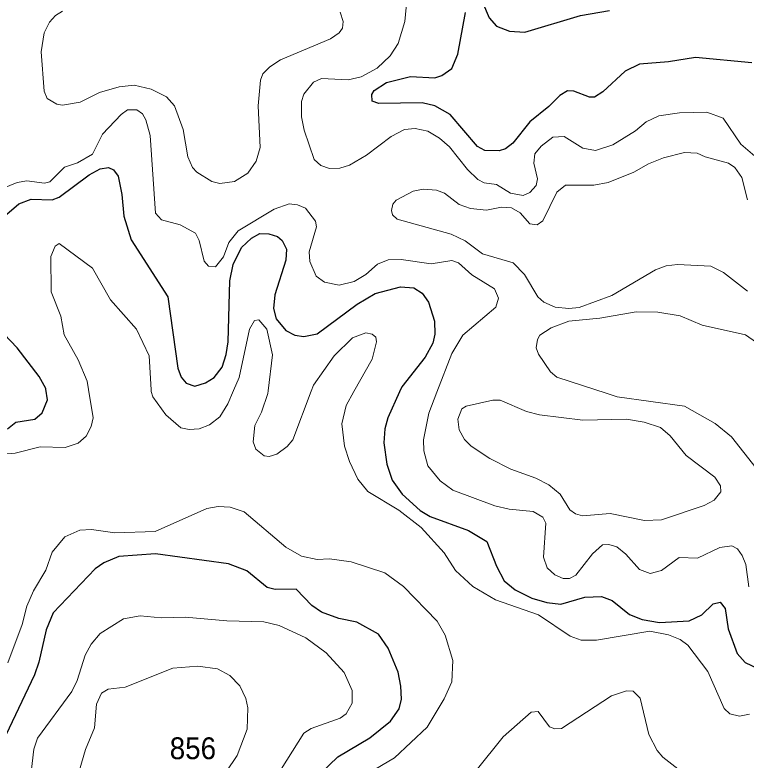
# Model space of a CAD drawing. Extents: x 473.9 to 500, y 7733.1 to 7760.8.
# Drawn here: x 494.647 to 497.324, y 7746.506 to 7749.235 of the extents above; entities that cross this region are included whole.
import ezdxf

# ---------------------------------------------------------------- set-up
doc = ezdxf.new("R2010")
doc.units = 0
doc.header["$LTSCALE"] = 0.032
doc.layers.add('1', color=7, linetype='Continuous', lineweight=25)
doc.layers.add('2', color=7, linetype='Continuous', lineweight=13)
doc.layers.add('21', color=7, linetype='Continuous')

msp = doc.modelspace()

# ---------------------------------------------------------------- linework, layer by layer
at = {"layer": '1'}
for points in [[(496.3589, 7749.2817), (496.3837, 7749.2245), (496.4099, 7749.194), (496.4582, 7749.175), (496.5134, 7749.1722), (496.717, 7749.2323), (496.8231, 7749.2508)], [(497.3442, 7749.0592), (497.1383, 7749.0787), (497.0392, 7749.0628), (496.9332, 7749.0539), (496.8806, 7749.0293), (496.799, 7748.9526), (496.7687, 7748.9331), (496.7501, 7748.9337), (496.6929, 7748.9551), (496.6695, 7748.9573), (496.6416, 7748.9401), (496.6022, 7748.8994), (496.5316, 7748.8437), (496.4703, 7748.7654), (496.4432, 7748.7448), (496.4201, 7748.7368), (496.3679, 7748.7384), (496.3407, 7748.753), (496.24, 7748.8697), (496.1842, 7748.9023), (496.1378, 7748.9131), (495.9789, 7748.9101), (495.9555, 7748.919), (495.9537, 7748.9432), (495.9624, 7748.9585), (496.0069, 7748.9879), (496.0954, 7749.0096), (496.1841, 7749.0043), (496.2094, 7749.0129), (496.2467, 7749.0384), (496.2691, 7749.0915), (496.2965, 7749.2439)], [(494.6097, 7748.498), (494.6614, 7748.5426), (494.7073, 7748.5604), (494.7835, 7748.5579), (494.8099, 7748.5673), (494.9193, 7748.6492), (494.9591, 7748.6714), (494.9904, 7748.6758), (495.0077, 7748.667), (495.0257, 7748.6441), (495.0392, 7748.5777), (495.0466, 7748.4979), (495.0732, 7748.4113), (495.2067, 7748.203), (495.2439, 7747.9411), (495.2563, 7747.9085), (495.274, 7747.887), (495.306, 7747.8754), (495.3448, 7747.8883), (495.3771, 7747.9069), (495.4056, 7747.945), (495.4207, 7747.991), (495.4276, 7748.0383), (495.4335, 7748.2606), (495.4456, 7748.321), (495.4768, 7748.3833), (495.5139, 7748.4176), (495.5437, 7748.434), (495.5772, 7748.4336), (495.608, 7748.4239), (495.6256, 7748.4083), (495.6417, 7748.3769), (495.6386, 7748.3368), (495.5987, 7748.2094), (495.5938, 7748.1602), (495.6041, 7748.1218), (495.6387, 7748.0789), (495.6718, 7748.0628), (495.7052, 7748.0578), (495.7532, 7748.0676), (495.9002, 7748.1763), (495.9658, 7748.2145), (496.0587, 7748.239), (496.1076, 7748.2357), (496.138, 7748.2166), (496.1613, 7748.1837), (496.1836, 7748.1138), (496.1845, 7748.0657), (496.1768, 7748.0332), (496.1491, 7747.9823), (496.0641, 7747.8732), (496.0556, 7747.8546), (496.012, 7747.76), (496.001, 7747.7189), (495.9981, 7747.6678), (496.0083, 7747.5896), (496.0283, 7747.5317), (496.0643, 7747.4806), (496.1306, 7747.4208), (496.1673, 7747.398), (496.3076, 7747.3469), (496.375, 7747.3063), (496.41, 7747.2164), (496.4387, 7747.1631), (496.4778, 7747.1296), (496.5391, 7747.0994), (496.5942, 7747.083), (496.6452, 7747.0777), (496.7331, 7747.1032), (496.7938, 7747.1056), (496.8333, 7747.0904), (496.8967, 7747.0393), (496.9434, 7747.0212), (497.0065, 7747.0102), (497.1153, 7747.0164), (497.1615, 7747.0381), (497.2035, 7747.079), (497.2287, 7747.0841)], [(494.6204, 7747.7197), (494.6508, 7747.7437), (494.7204, 7747.7548), (494.7468, 7747.7775), (494.7669, 7747.8251), (494.7603, 7747.8646), (494.76, 7747.8666), (494.7357, 7747.9106), (494.656, 7748.0154), (494.5833, 7748.0904)], [(495.7034, 7746.3978), (495.8295, 7746.518), (495.9467, 7746.5883), (496.0219, 7746.6492), (496.0532, 7746.6944), (496.0621, 7746.729), (496.0601, 7746.7772), (496.0499, 7746.8281), (496.0138, 7746.9158), (495.978, 7746.9673), (495.8989, 7747.0112), (495.8326, 7747.0247), (495.7691, 7747.0482), (495.7345, 7747.0728), (495.6762, 7747.1328), (495.5999, 7747.1311), (495.571, 7747.1379), (495.4963, 7747.199), (495.4296, 7747.2247), (495.1623, 7747.2616), (495.0276, 7747.2521), (494.9733, 7747.2289), (494.9413, 7747.207), (494.7874, 7747.0453), (494.7616, 7746.9839), (494.7349, 7746.8655), (494.7185, 7746.8184), (494.6146, 7746.5974)], [(497.2287, 7747.0841), (497.2465, 7747.0615), (497.2581, 7746.987), (497.2905, 7746.8971), (497.3198, 7746.8643), (497.3637, 7746.8436)]]:
    msp.add_lwpolyline(points, dxfattribs=at)
at = {"layer": '2'}
for points in [[(496.5081, 7748.5732), (496.4615, 7748.5825), (496.4095, 7748.6139), (496.3651, 7748.6204), (496.3416, 7748.6323), (496.3036, 7748.6692), (496.2379, 7748.7513), (496.202, 7748.7837), (496.1585, 7748.809), (496.112, 7748.8191), (496.0739, 7748.8152), (496.024, 7748.7893), (495.934, 7748.7213), (495.8721, 7748.6841), (495.837, 7748.6738), (495.7984, 7748.6721), (495.7669, 7748.6832), (495.7424, 7748.7055), (495.7057, 7748.8133), (495.6959, 7748.862), (495.6968, 7748.9178), (495.7052, 7748.9443), (495.7405, 7748.9888), (495.77, 7749.0016), (495.867, 7748.9977), (495.9147, 7749.0084), (495.9731, 7749.0395), (496.0209, 7749.0856), (496.0497, 7749.13), (496.0745, 7749.2111), (496.0836, 7749.3016)], [(494.8218, 7749.2485), (494.7964, 7749.233), (494.7739, 7749.208), (494.7544, 7749.1687), (494.743, 7749.1), (494.7544, 7748.9553), (494.7653, 7748.9284), (494.8009, 7748.9082), (494.8212, 7748.9044), (494.8856, 7748.9155), (494.9565, 7748.951), (495.0292, 7748.9721), (495.0837, 7748.9775), (495.1456, 7748.9633), (495.2024, 7748.9351), (495.2319, 7748.9021), (495.2637, 7748.8148), (495.2799, 7748.7152), (495.2978, 7748.6761), (495.3134, 7748.6588), (495.3682, 7748.6254), (495.3972, 7748.6173), (495.4511, 7748.625), (495.4993, 7748.6558), (495.5299, 7748.6996), (495.5453, 7748.749), (495.5374, 7748.9022), (495.5461, 7748.9954), (495.5545, 7749.0192), (495.5799, 7749.045), (495.6198, 7749.0703), (495.8021, 7749.1477), (495.834, 7749.169), (495.846, 7749.1862), (495.8483, 7749.2113), (495.838, 7749.2453)], [(494.6014, 7748.5988), (494.6552, 7748.6218), (494.691, 7748.627), (494.7553, 7748.6182), (494.7752, 7748.6242), (494.8283, 7748.6773), (494.8759, 7748.6927), (494.9307, 7748.7248), (494.9682, 7748.7982), (495.0357, 7748.8706), (495.0595, 7748.8876), (495.0932, 7748.887), (495.1141, 7748.8723), (495.1266, 7748.8508), (495.1426, 7748.7929), (495.1617, 7748.509), (495.1838, 7748.4845), (495.2522, 7748.4657), (495.3088, 7748.4359), (495.322, 7748.4086), (495.3397, 7748.3336), (495.3559, 7748.3154), (495.381, 7748.3124), (495.4102, 7748.3489), (495.4298, 7748.401), (495.4649, 7748.4448), (495.5967, 7748.5235), (495.6507, 7748.5433), (495.682, 7748.5397), (495.7113, 7748.5274), (495.7479, 7748.4798), (495.7512, 7748.4591), (495.7247, 7748.3668), (495.727, 7748.3325), (495.7505, 7748.2789), (495.7801, 7748.2566), (495.8338, 7748.2459), (495.889, 7748.2586), (495.932, 7748.2846), (495.9741, 7748.3228), (496.0133, 7748.3375), (496.0615, 7748.3391), (496.1704, 7748.3238), (496.246, 7748.3359), (496.2711, 7748.3267), (496.3197, 7748.2837), (496.4023, 7748.2314), (496.4169, 7748.1979), (496.4071, 7748.1648), (496.2863, 7748.0627), (496.2462, 7747.9949), (496.1919, 7747.8536), (496.1622, 7747.7761), (496.1426, 7747.6794), (496.1436, 7747.6388), (496.1592, 7747.5837), (496.2034, 7747.5284), (496.2508, 7747.4945), (496.4035, 7747.4372), (496.4567, 7747.4248), (496.5444, 7747.4172), (496.5802, 7747.3963), (496.5912, 7747.3742), (496.5824, 7747.2495), (496.5955, 7747.2108), (496.6232, 7747.1843), (496.6539, 7747.171), (496.6772, 7747.1719), (496.7009, 7747.1832), (496.7619, 7747.2619), (496.798, 7747.2949), (496.8209, 7747.2964)], [(497.364, 7748.7098), (497.304, 7748.7612), (497.2392, 7748.8569), (497.1803, 7748.8787), (497.0794, 7748.8769), (497.0044, 7748.865), (496.9583, 7748.8429), (496.9184, 7748.8105), (496.8361, 7748.7594), (496.7719, 7748.7378), (496.7262, 7748.7472), (496.6572, 7748.7902), (496.6163, 7748.7868), (496.5733, 7748.754), (496.5506, 7748.7267), (496.547, 7748.6917), (496.5599, 7748.6344), (496.5551, 7748.6099), (496.5317, 7748.5848), (496.5081, 7748.5732)], [(497.3282, 7748.2228), (497.2405, 7748.2919), (497.1952, 7748.3149), (497.0725, 7748.3214), (497.0312, 7748.3162), (496.9922, 7748.301), (496.8324, 7748.2077), (496.7122, 7748.1639), (496.6753, 7748.1598), (496.6249, 7748.1653), (496.5831, 7748.1829), (496.5609, 7748.203), (496.5131, 7748.2841), (496.4712, 7748.3276), (496.3584, 7748.3605), (496.2952, 7748.408), (496.2438, 7748.4322), (496.0462, 7748.4869), (496.0294, 7748.5031), (496.0254, 7748.519), (496.0309, 7748.542), (496.0426, 7748.5566), (496.1055, 7748.5901), (496.1419, 7748.5964), (496.1902, 7748.5932), (496.22, 7748.5817), (496.2733, 7748.5412), (496.3148, 7748.5257), (496.374, 7748.5201), (496.4288, 7748.5314), (496.4646, 7748.5283), (496.4965, 7748.5104), (496.5325, 7748.4694), (496.5595, 7748.4662), (496.5792, 7748.4805), (496.6315, 7748.5858), (496.663, 7748.6118), (496.7659, 7748.611), (496.8187, 7748.6217), (496.9132, 7748.6589), (496.9664, 7748.6894), (497.021, 7748.7114), (497.0987, 7748.7315), (497.1444, 7748.7283), (497.1737, 7748.7146), (497.259, 7748.6915), (497.2824, 7748.6764), (497.3079, 7748.6401), (497.3283, 7748.5581)], [(495.5504, 7747.7809), (495.5733, 7747.849), (495.5744, 7747.8583), (495.5896, 7747.9905), (495.5697, 7748.0838), (495.5397, 7748.1179), (495.5248, 7748.1158), (495.5062, 7748.0848), (495.468, 7747.9069), (495.4473, 7747.8593), (495.4263, 7747.8109), (495.3973, 7747.7636), (495.3596, 7747.7338), (495.3213, 7747.7195), (495.2849, 7747.7169), (495.2544, 7747.7236), (495.2001, 7747.7712), (495.1526, 7747.8361), (495.1459, 7747.856), (495.1456, 7747.8616), (495.1391, 7747.986), (495.0925, 7748.0842), (494.9974, 7748.1917), (494.9311, 7748.3072), (494.8097, 7748.3976), (494.7946, 7748.3886), (494.7786, 7748.3502), (494.7801, 7748.221), (494.8159, 7748.1315), (494.8272, 7748.0639), (494.8788, 7747.9717), (494.9119, 7747.8939), (494.9169, 7747.8634), (494.9341, 7747.7596), (494.9269, 7747.7275), (494.9081, 7747.6925), (494.8786, 7747.6665), (494.8316, 7747.6513), (494.7403, 7747.6534), (494.6479, 7747.6297), (494.5414, 7747.6222)], [(497.3602, 7747.5755), (497.2707, 7747.6903), (497.2105, 7747.7393), (497.0982, 7747.8021), (496.8512, 7747.8371), (496.8153, 7747.8488), (496.6314, 7747.9088), (496.6077, 7747.9283), (496.5637, 7747.9922), (496.5556, 7748.0163), (496.5597, 7748.0467), (496.5681, 7748.0618), (496.6099, 7748.0891), (496.6751, 7748.1138), (496.7881, 7748.1248), (496.9208, 7748.1479), (497.0007, 7748.1461), (497.0822, 7748.133), (497.1631, 7748.0985), (497.3212, 7748.0631), (497.4541, 7747.9713)], [(497.3356, 7746.6749), (497.2992, 7746.6669), (497.2641, 7746.6754), (497.2435, 7746.695), (497.1836, 7746.8305), (497.1098, 7746.9271), (497.082, 7746.9476), (497.0392, 7746.9649), (496.9717, 7746.9788), (496.7755, 7746.945), (496.7203, 7746.9456), (496.6797, 7746.9602), (496.564, 7747.0383), (496.4063, 7747.0934), (496.3232, 7747.1415), (496.2602, 7747.2007), (496.2187, 7747.2653), (496.1347, 7747.3582), (496.0528, 7747.421), (495.9394, 7747.4899), (495.9031, 7747.535), (495.8716, 7747.5992), (495.8536, 7747.6555), (495.8437, 7747.738), (495.8601, 7747.8051), (495.8884, 7747.8559), (495.9544, 7747.9744), (495.9714, 7748.0376), (495.9682, 7748.0551), (495.9553, 7748.0664), (495.9312, 7748.0704), (495.8835, 7748.0524), (495.8156, 7747.987), (495.7397, 7747.8798), (495.7312, 7747.8571), (495.6642, 7747.6793), (495.6438, 7747.6546), (495.6065, 7747.6269), (495.5781, 7747.6186), (495.5594, 7747.6201), (495.5297, 7747.6446), (495.5196, 7747.6721), (495.5253, 7747.7321), (495.5504, 7747.7809)], [(494.6215, 7746.8623), (494.6739, 7747.0026), (494.691, 7747.0702), (494.715, 7747.126), (494.7609, 7747.2019), (494.7835, 7747.2682), (494.8299, 7747.3236), (494.8846, 7747.3486), (494.9277, 7747.3504), (495.0125, 7747.3389), (495.1608, 7747.3434), (495.3492, 7747.4282), (495.3916, 7747.4354), (495.435, 7747.4328), (495.4859, 7747.415), (495.6394, 7747.2857), (495.6966, 7747.253), (495.7533, 7747.241), (495.7984, 7747.2439), (495.8778, 7747.2318), (496.001, 7747.1915), (496.0696, 7747.1419), (496.1934, 7747.0156), (496.2222, 7746.9635), (496.2499, 7746.8716), (496.2468, 7746.7935), (496.2191, 7746.7303), (496.1566, 7746.6276), (496.0364, 7746.5149)], [(496.8209, 7747.2964), (496.8506, 7747.2876), (496.8839, 7747.2602), (496.9336, 7747.2045), (496.9722, 7747.1895), (497.0136, 7747.2009), (497.0789, 7747.2487), (497.1452, 7747.2454), (497.2279, 7747.2851), (497.2711, 7747.2907), (497.2916, 7747.2804), (497.3096, 7747.2557), (497.3222, 7747.2221), (497.3339, 7747.1408)], [(494.7021, 7746.4207), (494.7163, 7746.546), (494.7305, 7746.5862), (494.8555, 7746.7576), (494.875, 7746.7984), (494.9047, 7746.8911), (494.9263, 7746.9313), (494.9597, 7746.9703), (495.0447, 7747.0236), (495.1053, 7747.0351), (495.1825, 7747.0271), (495.271, 7747.0302), (495.4232, 7747.0158), (495.5582, 7747.0125), (495.6145, 7746.9996), (495.7126, 7746.9546), (495.7871, 7746.8995), (495.8528, 7746.8271), (495.8821, 7746.7614), (495.882, 7746.7153), (495.8604, 7746.6757), (495.8373, 7746.6602), (495.732, 7746.6226), (495.7049, 7746.6052), (495.622, 7746.4727)], [(495.4208, 7746.4635), (495.4606, 7746.5232), (495.4971, 7746.6193), (495.5004, 7746.6978), (495.4921, 7746.7325), (495.4707, 7746.7785), (495.4342, 7746.8165), (495.3884, 7746.8402), (495.3169, 7746.8502), (495.2254, 7746.8436), (495.0504, 7746.7739), (494.989, 7746.7656), (494.9643, 7746.7518), (494.9454, 7746.7111), (494.9381, 7746.6248), (494.9052, 7746.5455), (494.883, 7746.4656)], [(496.3351, 7746.4679), (496.4347, 7746.592), (496.5365, 7746.6821), (496.563, 7746.6849), (496.6035, 7746.6279), (496.624, 7746.6208), (496.6476, 7746.6218), (496.8311, 7746.7414), (496.8854, 7746.76), (496.9102, 7746.7588), (496.9365, 7746.733), (496.9671, 7746.6002), (496.9978, 7746.5417), (497.0186, 7746.5172), (497.1333, 7746.428)], [(496.0364, 7746.5149), (495.9147, 7746.4429)]]:
    msp.add_lwpolyline(points, dxfattribs=at)
msp.add_lwpolyline([(496.3853, 7747.611), (496.3179, 7747.6564), (496.2935, 7747.6798), (496.2734, 7747.7155), (496.2691, 7747.7551), (496.2836, 7747.793), (496.2987, 7747.8027), (496.3971, 7747.8244), (496.4233, 7747.8245), (496.5193, 7747.7824), (496.5671, 7747.77), (496.7262, 7747.7507), (496.886, 7747.7547), (496.9508, 7747.7433), (497.01, 7747.7239), (497.0456, 7747.6943), (497.1043, 7747.622), (497.2089, 7747.5422), (497.2298, 7747.5107), (497.2306, 7747.4887), (497.2065, 7747.4585), (497.1701, 7747.439), (497.014, 7747.3861), (496.9519, 7747.3841), (496.8259, 7747.4097), (496.7251, 7747.4002), (496.699, 7747.4079), (496.6789, 7747.4229), (496.6436, 7747.4806), (496.6018, 7747.5142), (496.5542, 7747.5389), (496.4625, 7747.5718)], close=True, dxfattribs=at)

# ---------------------------------------------------------------- texts
at = {"layer": '21', "width": 0.95}
msp.add_text('856', height=0.08, dxfattribs=at).set_placement((495.214, 7746.5098))

doc.saveas('drawing.dxf')
